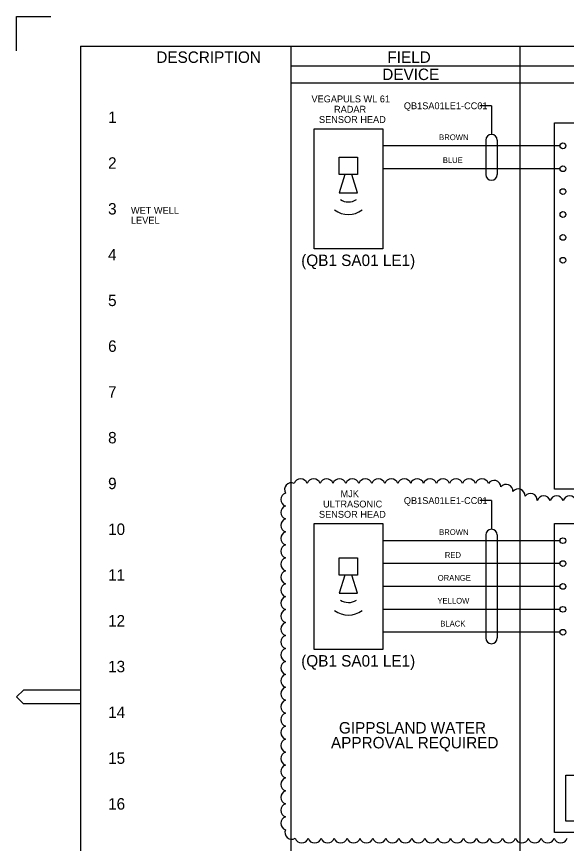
# Model space of a CAD drawing. Extents: x 0 to 841, y 0 to 594.
# Drawn here: x 0 to 240.3, y 232.7 to 594 of the extents above; entities that cross this region are included whole.
import ezdxf

# ---------------------------------------------------------------- set-up
doc = ezdxf.new("R2010")
doc.units = 0
for name, color, linetype in [('A1BORDER', 7, 'Continuous'), ('Level 1', 7, 'Continuous'), ('Level 10', 7, 'Continuous'), ('Level 3', 7, 'Continuous')]:
    doc.layers.add(name, color=color, linetype=linetype)

msp = doc.modelspace()

# ---------------------------------------------------------------- linework, layer by layer
at = {"layer": 'A1BORDER'}
for p, q in [((0, 594), (15, 594)), ((0, 579), (0, 594)), ((28, 581), (829, 581)), ((28, 581), (28, 15)), ((3, 299.76), (0, 296.76)), ((3, 293.76), (0, 296.76)), ((28, 299.76), (3, 299.76)), ((28, 293.76), (3, 293.76))]:
    msp.add_line(p, q, dxfattribs=at)
at = {"layer": 'Level 1'}
for p, q in [((120, 57.5), (120, 581)), ((220, 57.5), (220, 581)), ((120, 572.5), (829, 572.5)), ((120, 565), (829, 565)), ((207.5, 555), (202.5, 555)), ((207.5, 555), (207.5, 542.5)), ((205, 540), (205, 525)), ((210, 540), (210, 525)), ((237.5, 537.5), (160, 537.5)), ((237.5, 537.5), (237.5, 537.5)), ((240, 537.5), (240, 537.5)), ((237.5, 527.5), (160, 527.5)), ((237.5, 527.5), (237.5, 527.5)), ((240, 527.5), (240, 527.5)), ((237.5, 517.5), (237.5, 517.5)), ((240, 517.5), (240, 517.5)), ((237.5, 507.5), (237.5, 507.5)), ((240, 507.5), (240, 507.5)), ((237.5, 497.5), (237.5, 497.5)), ((240, 497.5), (240, 497.5)), ((237.5, 487.5), (237.5, 487.5)), ((240, 487.5), (240, 487.5)), ((207.5, 382.5), (202.5, 382.5)), ((207.5, 382.5), (207.5, 370)), ((237.5, 365), (160, 365)), ((205, 367.5), (205, 322.5)), ((210, 367.5), (210, 322.5)), ((237.5, 365), (237.5, 365)), ((240, 365), (240, 365)), ((237.5, 355), (160, 355)), ((237.5, 355), (237.5, 355)), ((240, 355), (240, 355)), ((237.5, 345), (160, 345)), ((237.5, 345), (237.5, 345)), ((240, 345), (240, 345)), ((237.5, 335), (160, 335)), ((237.5, 335), (237.5, 335)), ((240, 335), (240, 335)), ((237.5, 325), (160, 325)), ((237.5, 325), (237.5, 325)), ((240, 325), (240, 325))]:
    msp.add_line(p, q, dxfattribs=at)
for points in [[(235, 387.5), (235, 547.5), (320, 547.5), (320, 387.5)], [(130, 492.5), (130, 545), (160, 545), (160, 492.5)], [(130, 317.5), (130, 372.5), (160, 372.5), (160, 317.5)], [(235, 237.5), (235, 372.5), (320, 372.5), (320, 237.5)], [(240, 262.5), (282.5, 262.5), (282.5, 242.5), (240, 242.5)]]:
    msp.add_lwpolyline(points, close=True, dxfattribs=at)
for centre, radius, start, end in [((207.5, 540), 2.5, 0, 180), ((207.5, 525), 2.5, 180, 0), ((120.06, 387.3), 2.97, 65.3442, 210.3442), ((124.13, 389.11), 2.97, 17.5, 162.5), ((129.78, 389.11), 2.97, 17.5, 162.5), ((135.44, 389.11), 2.97, 17.5, 162.5), ((141.1, 389.11), 2.97, 17.5, 162.5), ((146.76, 389.11), 2.97, 17.5, 162.5), ((152.41, 389.11), 2.97, 17.5, 162.5), ((158.07, 389.11), 2.97, 17.5, 162.5), ((163.73, 389.11), 2.97, 17.5, 162.5), ((169.39, 389.11), 2.97, 17.5, 162.5), ((175.05, 389.11), 2.97, 17.5, 162.5), ((180.7, 389.11), 2.97, 17.5, 162.5), ((186.36, 389.11), 2.97, 17.5, 162.5), ((192.02, 389.11), 2.97, 17.5, 162.5), ((197.68, 389.11), 2.97, 17.5, 162.5), ((203.33, 389.11), 2.97, 17.5, 162.5), ((208.64, 388.37), 2.97, 1.7022, 146.7022), ((213.94, 386.63), 2.97, 356.944, 141.944), ((219.24, 384.64), 2.97, 356.944, 141.944), ((118.39, 382.98), 2.97, 107.5, 252.5), ((224.54, 382.66), 2.97, 356.944, 141.944), ((230.33, 381.61), 2.97, 17.5, 162.5), ((235.99, 381.61), 2.97, 17.5, 162.5), ((241.64, 381.61), 2.97, 17.5, 162.5), ((118.39, 377.32), 2.97, 107.5, 252.5), ((118.39, 371.66), 2.97, 107.5, 252.5), ((118.39, 366), 2.97, 107.5, 252.5), ((207.5, 367.5), 2.5, 0, 180), ((118.39, 360.35), 2.97, 107.5, 252.5), ((118.39, 354.69), 2.97, 107.5, 252.5), ((118.39, 349.03), 2.97, 107.5, 252.5), ((118.39, 343.37), 2.97, 107.5, 252.5), ((118.39, 337.72), 2.97, 107.5, 252.5), ((118.39, 332.06), 2.97, 107.5, 252.5), ((118.39, 326.4), 2.97, 107.5, 252.5), ((118.39, 320.74), 2.97, 107.5, 252.5), ((207.5, 322.5), 2.5, 180, 0), ((118.39, 315.08), 2.97, 107.5, 252.5), ((118.39, 309.43), 2.97, 107.5, 252.5), ((118.39, 303.77), 2.97, 107.5, 252.5), ((118.39, 298.11), 2.97, 107.5, 252.5), ((118.39, 292.45), 2.97, 107.5, 252.5), ((118.39, 286.8), 2.97, 107.5, 252.5), ((118.39, 281.14), 2.97, 107.5, 252.5), ((118.39, 275.48), 2.97, 107.5, 252.5), ((118.39, 269.82), 2.97, 107.5, 252.5), ((118.39, 264.16), 2.97, 107.5, 252.5), ((118.39, 258.51), 2.97, 107.5, 252.5), ((118.39, 252.85), 2.97, 107.5, 252.5), ((118.39, 247.19), 2.97, 107.5, 252.5), ((118.39, 241.53), 2.97, 107.5, 252.5), ((120.22, 237.53), 2.97, 156.6035, 301.6035), ((124.61, 235.89), 2.97, 197.5, 342.5), ((130.26, 235.89), 2.97, 197.5, 342.5), ((135.92, 235.89), 2.97, 197.5, 342.5), ((141.58, 235.89), 2.97, 197.5, 342.5), ((147.24, 235.89), 2.97, 197.5, 342.5), ((152.89, 235.89), 2.97, 197.5, 342.5), ((158.55, 235.89), 2.97, 197.5, 342.5), ((164.21, 235.89), 2.97, 197.5, 342.5), ((169.87, 235.89), 2.97, 197.5, 342.5), ((175.53, 235.89), 2.97, 197.5, 342.5), ((181.18, 235.89), 2.97, 197.5, 342.5), ((186.84, 235.89), 2.97, 197.5, 342.5), ((192.5, 235.89), 2.97, 197.5, 342.5), ((198.16, 235.89), 2.97, 197.5, 342.5), ((203.81, 235.89), 2.97, 197.5, 342.5), ((209.47, 235.89), 2.97, 197.5, 342.5), ((215.13, 235.89), 2.97, 197.5, 342.5), ((220.79, 235.89), 2.97, 197.5, 342.5), ((226.45, 235.89), 2.97, 197.5, 342.5), ((232.1, 235.89), 2.97, 197.5, 342.5), ((237.76, 235.89), 2.97, 197.5, 342.5)]:
    msp.add_arc(centre, radius, start, end, dxfattribs=at)
at = {"layer": 'Level 10'}
for centre in [(238.75, 537.5), (238.75, 527.5), (238.75, 517.5), (238.75, 507.5), (238.75, 497.5), (238.75, 487.5), (238.75, 365), (238.75, 355), (238.75, 345), (238.75, 335), (238.75, 325)]:
    msp.add_circle(centre, 1.25, dxfattribs=at)
at = {"layer": 'Level 3'}
for p, q in [((143.5, 525), (141, 517)), ((149, 517), (146.5, 525)), ((141, 517), (149, 517)), ((143.5, 350), (141, 342)), ((149, 342), (146.5, 350)), ((141, 342), (149, 342))]:
    msp.add_line(p, q, dxfattribs=at)
for points in [[(141, 532.5), (149, 532.5), (149, 525), (141, 525)], [(141, 357.5), (149, 357.5), (149, 350), (141, 350)]]:
    msp.add_lwpolyline(points, close=True, dxfattribs=at)
for centre, radius, start, end in [((145, 519.61), 6.61, 237.9927, 301.9255), ((145, 517.33), 9.83, 232.2557, 307.7162), ((145, 344.61), 6.61, 237.9927, 301.9255), ((145, 342.33), 9.83, 232.2557, 307.7162)]:
    msp.add_arc(centre, radius, start, end, dxfattribs=at)

# ---------------------------------------------------------------- texts
at = {"layer": 'Level 1'}
for s, height, p in [('DESCRIPTION', 5, (61.07, 573.75)), ('FIELD', 5, (162.03, 573.75)), ('DEVICE', 5, (159.79, 566.25)), ('VEGAPULS WL 61', 3, (128.86, 556.51)), ('QB1SA01LE1-CC01', 3, (169.22, 553.5)), ('RADAR', 3, (138.72, 552.01)), ('1', 5, (40, 547.5)), ('SENSOR HEAD', 3, (132.15, 547.51)), ('BROWN', 2.5, (184.65, 540)), ('2', 5, (40, 527.5)), ('BLUE', 2.5, (186.26, 530)), ('3', 5, (40, 507.5)), ('WET WELL', 3, (50, 507.84)), ('LEVEL', 3, (50, 503.5)), ('4', 5, (40, 487.5)), ('(QB1 SA01 LE1)', 5, (124.38, 485)), ('5', 5, (40, 467.5)), ('6', 5, (40, 447.5)), ('7', 5, (40, 427.5)), ('8', 5, (40, 407.5)), ('9', 5, (40, 387.5)), ('MJK', 3, (141.56, 384.01)), ('QB1SA01LE1-CC01', 3, (169.22, 381)), ('ULTRASONIC', 3, (133.94, 379.51)), ('SENSOR HEAD', 3, (132.15, 375.01)), ('10', 5, (40, 367.5)), ('BROWN', 2.5, (184.65, 367.5)), ('RED', 2.5, (187.14, 357.5)), ('11', 5, (40, 347.5)), ('ORANGE', 2.5, (184.02, 347.5)), ('YELLOW', 2.5, (183.9, 337.5)), ('12', 5, (40, 327.5)), ('BLACK', 2.5, (185.14, 327.5)), ('(QB1 SA01 LE1)', 5, (124.38, 310)), ('13', 5, (40, 307.5)), ('14', 5, (40, 287.5)), ('GIPPSLAND WATER', 5, (140.86, 280.75)), ('APPROVAL REQUIRED', 5, (137.38, 274.25)), ('15', 5, (40, 267.5)), ('16', 5, (40, 247.5))]:
    msp.add_text(s, height=height, dxfattribs=at).set_placement(p)

doc.saveas('drawing.dxf')
